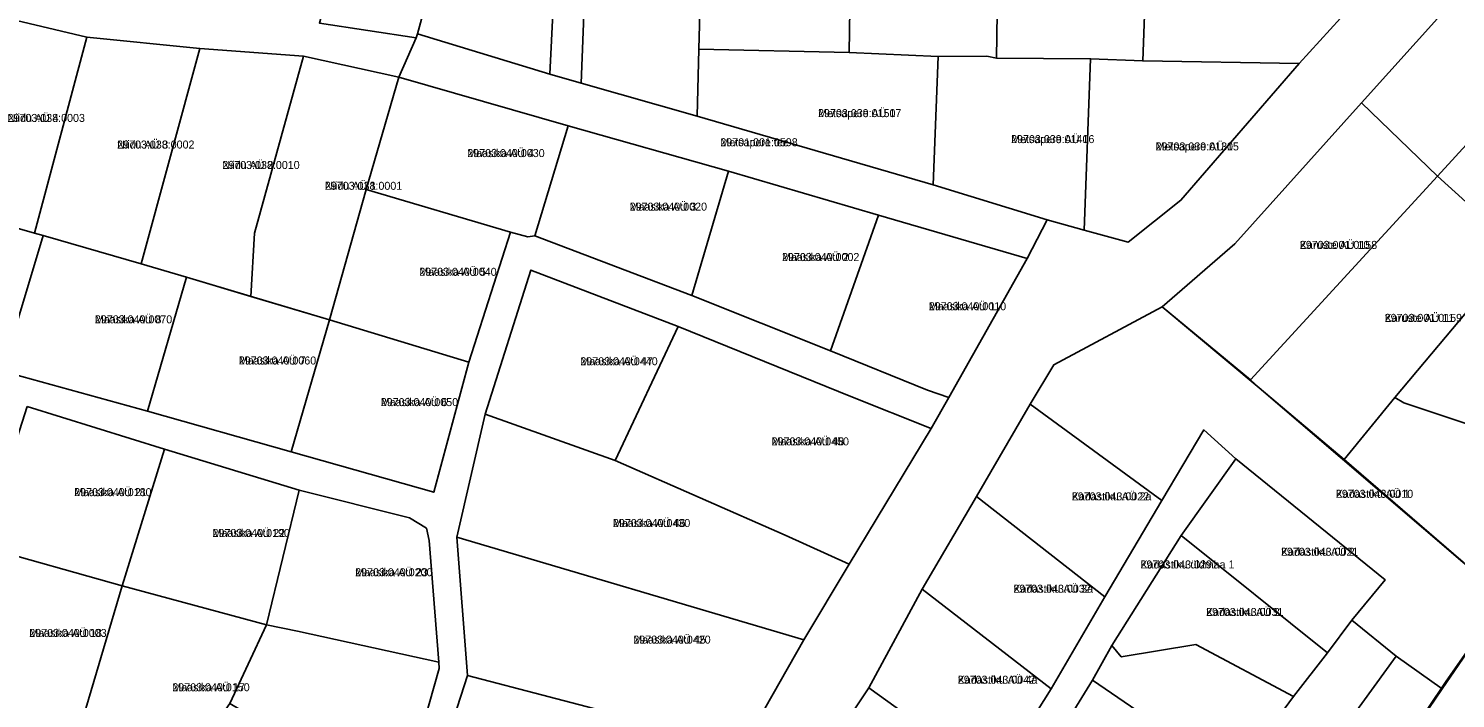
# Model space of a CAD drawing. Extents: x 504287 to 537970, y 6539941 to 6586214.
# Drawn here: x 519484 to 519751.5, y 6560529.1 to 6560654.7 of the extents above; entities that cross this region are included whole.
import ezdxf

# ---------------------------------------------------------------- set-up
doc = ezdxf.new("R2010")
doc.units = 0
for name, color, linetype in [('L_AADRESS', 7, 'Continuous'), ('PIIR', 7, 'Continuous'), ('TUNNUS', 7, 'Continuous')]:
    doc.layers.add(name, color=color, linetype=linetype)

msp = doc.modelspace()

# ---------------------------------------------------------------- linework, layer by layer
at = {"layer": 'PIIR'}
for points in [[(519545.97, 6560683.73), (519553.91, 6560699.22), (519557.93, 6560704.58), (519570.16, 6560715.51), (519573.25, 6560713.46), (519565.9, 6560686.67), (519556.9, 6560653.64), (519556.68, 6560652.92), (519538.51, 6560655.67)], [(519583.75, 6560686.55), (519581.71, 6560646.09), (519556.9, 6560653.64), (519565.9, 6560686.67)], [(519588.8, 6560675), (519593.29, 6560680.01), (519610.46, 6560680.42), (519609.63, 6560650.78), (519609.34, 6560638.23), (519587.61, 6560644.43)], [(519610.46, 6560680.42), (519637.77, 6560679.93), (519638.26, 6560678.69), (519637.86, 6560650.16), (519609.63, 6560650.78)], [(519638.26, 6560678.69), (519665.88, 6560678.74), (519665.47, 6560649.08), (519663.63, 6560649.49), (519654.54, 6560649.41), (519637.86, 6560650.16)], [(519665.88, 6560678.74), (519693.95, 6560677.88), (519692.88, 6560648.58), (519683.09, 6560649), (519665.47, 6560649.08)], [(519693.95, 6560677.88), (519708.11, 6560677.84), (519729.98, 6560656.58), (519722.23, 6560648.11), (519692.88, 6560648.58)], [(519758.97, 6560668.59), (519775.14, 6560656.47), (519748.13, 6560626.98), (519733.89, 6560640.72)], [(519465.19, 6560621.98), (519475.62, 6560657.61), (519494.94, 6560653.06), (519485.11, 6560616.29), (519474.38, 6560619.37)], [(519775.14, 6560656.47), (519790.1, 6560645.25), (519763.37, 6560613.2), (519748.13, 6560626.98)], [(519485.11, 6560616.29), (519494.94, 6560653.06), (519516.09, 6560650.93), (519505.1, 6560610.52), (519486.72, 6560615.84)], [(519556.68, 6560652.92), (519556.9, 6560653.64), (519581.71, 6560646.09), (519587.61, 6560644.43), (519609.34, 6560638.23), (519653.58, 6560625.33), (519674.93, 6560618.79), (519671.23, 6560611.54), (519643.32, 6560619.67), (519615.22, 6560627.91), (519585.19, 6560636.42), (519553.44, 6560645.52)], [(519505.1, 6560610.52), (519516.09, 6560650.93), (519535.54, 6560649.45), (519526.34, 6560616.28), (519525.67, 6560604.45), (519513.58, 6560608.07)], [(519526.34, 6560616.28), (519535.54, 6560649.45), (519553.44, 6560645.52), (519547.32, 6560624.51), (519540.44, 6560600.03), (519525.67, 6560604.45)], [(519609.63, 6560650.78), (519637.86, 6560650.16), (519654.54, 6560649.41), (519653.58, 6560625.33), (519609.34, 6560638.23)], [(519674.93, 6560618.79), (519653.58, 6560625.33), (519654.54, 6560649.41), (519663.63, 6560649.49), (519665.47, 6560649.08), (519683.09, 6560649), (519681.89, 6560616.88)], [(519722.23, 6560648.11), (519700.04, 6560622.46), (519690.16, 6560614.62), (519681.89, 6560616.88), (519683.09, 6560649), (519692.88, 6560648.58)], [(519553.44, 6560645.52), (519585.19, 6560636.42), (519578.93, 6560615.81), (519577.6, 6560615.6), (519574.35, 6560616.46), (519547.32, 6560624.51)], [(519790.1, 6560645.25), (519792.1, 6560643.72), (519790.9, 6560641.63), (519782.76, 6560605.26), (519775.79, 6560574.07), (519768.41, 6560575.6), (519741.84, 6560584.51), (519740.15, 6560585.49), (519763.37, 6560613.2)], [(519733.89, 6560640.72), (519748.13, 6560626.98), (519713.09, 6560588.78), (519696.51, 6560602.52), (519710.13, 6560614.32)], [(519585.19, 6560636.42), (519615.22, 6560627.91), (519608.32, 6560604.61), (519578.93, 6560615.81)], [(519615.22, 6560627.91), (519643.32, 6560619.67), (519634.31, 6560594.22), (519608.32, 6560604.61)], [(519547.32, 6560624.51), (519574.35, 6560616.46), (519566.52, 6560592.11), (519540.44, 6560600.03)], [(519748.13, 6560626.98), (519763.37, 6560613.2), (519740.15, 6560585.49), (519730.65, 6560573.89), (519714.73, 6560587.31), (519713.09, 6560588.78)], [(519459.75, 6560623.53), (519465.19, 6560621.98), (519474.38, 6560619.37), (519485.11, 6560616.29), (519486.72, 6560615.84), (519479.12, 6560590.42), (519451.97, 6560598.83)], [(519634.31, 6560594.22), (519643.32, 6560619.67), (519671.23, 6560611.54), (519656.53, 6560585.5), (519652.5, 6560586.87)], [(519486.72, 6560615.84), (519505.1, 6560610.52), (519513.58, 6560608.07), (519506.3, 6560582.95), (519479.12, 6560590.42)], [(519578.18, 6560609.38), (519605.78, 6560598.8), (519593.95, 6560573.7), (519569.61, 6560582.35)], [(519513.58, 6560608.07), (519540.44, 6560600.03), (519533.25, 6560575.28), (519506.3, 6560582.95)], [(519696.51, 6560602.52), (519714.73, 6560587.31), (519760.67, 6560547.92), (519749.01, 6560530.86), (519740.41, 6560536.98), (519732.08, 6560543.74), (519738.31, 6560551.32), (519710.34, 6560574.02), (519704.32, 6560579.41), (519696.48, 6560566.19), (519671.78, 6560584.27), (519676.22, 6560591.64)], [(519540.44, 6560600.03), (519566.52, 6560592.11), (519559.96, 6560567.73), (519533.25, 6560575.28)], [(519605.78, 6560598.8), (519638.16, 6560585.71), (519653.23, 6560579.69), (519637.86, 6560554.23), (519625.83, 6560559.7), (519593.95, 6560573.7)], [(519671.78, 6560584.27), (519696.48, 6560566.19), (519685.78, 6560548.14), (519661.74, 6560566.94)], [(519740.15, 6560585.49), (519741.84, 6560584.51), (519768.41, 6560575.6), (519775.79, 6560574.07), (519779.93, 6560573.6), (519772.35, 6560544.8), (519760.67, 6560547.92), (519730.65, 6560573.89)], [(519483.75, 6560583.81), (519509.49, 6560575.79), (519501.54, 6560550.19), (519475.31, 6560557.55)], [(519569.61, 6560582.35), (519593.95, 6560573.7), (519625.83, 6560559.7), (519637.86, 6560554.23), (519629.31, 6560540.07), (519564.26, 6560559.32)], [(519509.49, 6560575.79), (519534.7, 6560568.1), (519528.63, 6560542.91), (519501.54, 6560550.19)], [(519710.34, 6560574.02), (519738.31, 6560551.32), (519732.08, 6560543.74), (519727.5, 6560537.65), (519700.08, 6560559.64)], [(519528.63, 6560542.91), (519534.7, 6560568.1), (519555.39, 6560562.91), (519558.59, 6560560.98), (519559.1, 6560558.72), (519560.92, 6560535.88), (519534.41, 6560541.68)], [(519661.74, 6560566.94), (519685.78, 6560548.14), (519675.73, 6560530.86), (519651.54, 6560549.59)], [(519466.73, 6560529.79), (519475.31, 6560557.55), (519501.54, 6560550.19), (519493.26, 6560522.11), (519482.99, 6560526.65)], [(519564.26, 6560559.32), (519629.31, 6560540.07), (519617.6, 6560519.39), (519596.92, 6560525.41), (519566.31, 6560533.39)], [(519700.08, 6560559.64), (519727.5, 6560537.65), (519721.17, 6560529.45), (519702.86, 6560539.2), (519688.86, 6560536.86), (519687.1, 6560538.98)], [(519501.54, 6560550.19), (519528.63, 6560542.91), (519521.74, 6560528.12), (519511.51, 6560513.6), (519509.75, 6560512.35), (519493.26, 6560522.11)], [(519651.54, 6560549.59), (519675.73, 6560530.86), (519665.15, 6560514.09), (519641.52, 6560531.1)], [(519521.74, 6560528.12), (519528.63, 6560542.91), (519534.41, 6560541.68), (519560.92, 6560535.88), (519560.97, 6560534.7), (519557.09, 6560521.02), (519548.79, 6560510.86), (519532.38, 6560521.8)], [(519706.2, 6560516.97), (519709.33, 6560513.37), (519721.17, 6560529.45), (519727.5, 6560537.65), (519732.08, 6560543.74), (519740.41, 6560536.98), (519701.98, 6560484.01), (519687.73, 6560493.58)], [(519687.1, 6560538.98), (519688.86, 6560536.86), (519702.86, 6560539.2), (519721.17, 6560529.45), (519709.33, 6560513.37), (519706.2, 6560516.97), (519683.46, 6560532.48)], [(519740.41, 6560536.98), (519749.01, 6560530.86), (519722.54, 6560491.81), (519721.71, 6560469.51), (519720.49, 6560468.45), (519701.98, 6560484.01)], [(519566.31, 6560533.39), (519596.92, 6560525.41), (519617.6, 6560519.39), (519601.54, 6560491.69), (519560.51, 6560515.59)], [(519683.46, 6560532.48), (519706.2, 6560516.97), (519672.52, 6560507.08), (519669.12, 6560509.28)]]:
    msp.add_lwpolyline(points, close=True, dxfattribs=at)
for points in [[(519588.8, 6560675), (519587.61, 6560644.43), (519581.71, 6560646.09), (519583.75, 6560686.55)], [(519758.97, 6560668.59), (519733.89, 6560640.72), (519710.13, 6560614.32), (519696.51, 6560602.52), (519676.22, 6560591.64), (519671.78, 6560584.27), (519661.74, 6560566.94), (519651.54, 6560549.59), (519641.52, 6560531.1), (519637.54, 6560525.07), (519619.51, 6560495.06), (519601.79, 6560464.9), (519597.62, 6560457.87), (519583.8, 6560445.64), (519571.46, 6560440.43), (519547, 6560424.1), (519538.39, 6560413.48), (519516.93, 6560385.7), (519503.46, 6560367.79), (519487.87, 6560351.07), (519467.89, 6560339.35)], [(519538.51, 6560655.67), (519556.68, 6560652.92), (519553.44, 6560645.52), (519535.54, 6560649.45), (519516.09, 6560650.93), (519494.94, 6560653.06), (519475.62, 6560657.61)], [(519476.35, 6560360.51), (519492.61, 6560372.35), (519498.16, 6560379.12), (519511.54, 6560396.76), (519526.77, 6560415.79), (519537.12, 6560428.03), (519550.29, 6560439.35), (519558.78, 6560445.49), (519583.53, 6560463.78), (519586.02, 6560465.87), (519589.85, 6560471.99), (519601.54, 6560491.69), (519617.6, 6560519.39), (519629.31, 6560540.07), (519637.86, 6560554.23), (519653.23, 6560579.69), (519656.53, 6560585.5), (519671.23, 6560611.54), (519674.93, 6560618.79), (519681.89, 6560616.88), (519690.16, 6560614.62), (519700.04, 6560622.46), (519722.23, 6560648.11), (519729.98, 6560656.58)], [(519479.12, 6560590.42), (519506.3, 6560582.95), (519533.25, 6560575.28), (519559.96, 6560567.73), (519566.52, 6560592.11), (519574.35, 6560616.46), (519577.6, 6560615.6), (519578.93, 6560615.81), (519608.32, 6560604.61), (519634.31, 6560594.22), (519652.5, 6560586.87), (519656.53, 6560585.5), (519653.23, 6560579.69), (519638.16, 6560585.71), (519605.78, 6560598.8), (519578.18, 6560609.38), (519569.61, 6560582.35), (519564.26, 6560559.32), (519566.31, 6560533.39), (519560.51, 6560515.59)], [(519482.99, 6560526.65), (519493.26, 6560522.11), (519509.75, 6560512.35), (519511.51, 6560513.6), (519519.61, 6560505.79), (519530.53, 6560492.35), (519537.53, 6560498.72), (519544.75, 6560505.81), (519548.79, 6560510.86), (519557.09, 6560521.02), (519560.97, 6560534.7), (519560.92, 6560535.88), (519559.1, 6560558.72), (519558.59, 6560560.98), (519555.39, 6560562.91), (519534.7, 6560568.1), (519509.49, 6560575.79), (519483.75, 6560583.81)], [(519637.54, 6560525.07), (519641.52, 6560531.1), (519665.15, 6560514.09), (519675.73, 6560530.86), (519685.78, 6560548.14), (519696.48, 6560566.19), (519704.32, 6560579.41), (519710.34, 6560574.02), (519700.08, 6560559.64), (519687.1, 6560538.98), (519683.46, 6560532.48), (519669.12, 6560509.28)], [(519703.18, 6560322.99), (519713.19, 6560344.19), (519691.96, 6560356.34), (519698.12, 6560365.63), (519712.14, 6560374.97), (519724.32, 6560363.49), (519737.28, 6560371.88), (519762.93, 6560388.21), (519782.49, 6560401.44), (519769.22, 6560411.65), (519785.83, 6560421.92), (519748.28, 6560451.06), (519742.16, 6560456.22), (519722.85, 6560470.8), (519723.75, 6560493.59), (519749.63, 6560532.14), (519760.67, 6560547.92), (519772.35, 6560544.8), (519797.54, 6560537.62), (519829.04, 6560528.69), (519858.47, 6560520.41), (519883.63, 6560513.22), (519926.01, 6560463.67)]]:
    msp.add_lwpolyline(points, dxfattribs=at)

# ---------------------------------------------------------------- texts
at = {"layer": 'L_AADRESS'}
for s, p in [('Niidu AÜ 4', (519480.06, 6560637.15)), ('Metsapere AÜ 17', (519632.01, 6560638.05)), ('Niidu AÜ 3', (519500.6, 6560632.16)), ('Metsapere tee', (519613.69, 6560632.59)), ('Metsapere AÜ 16', (519668.2, 6560633.18)), ('Metsapere AÜ 15', (519695.29, 6560631.81)), ('Niidu AÜ 2', (519520.32, 6560628.33)), ('Maasika AÜ 4', (519566.25, 6560630.56)), ('Niidu AÜ 1', (519539.55, 6560624.43)), ('Maasika AÜ 3', (519596.69, 6560620.52)), ('Karuste AÜ 10', (519722.32, 6560613.35)), ('Maasika AÜ 2', (519625.25, 6560611.07)), ('Maasika AÜ 5', (519557.25, 6560608.31)), ('Maasika AÜ 1', (519652.77, 6560601.85)), ('Maasika AÜ 8', (519496.43, 6560599.4)), ('Karuste AÜ 11', (519738.23, 6560599.67)), ('Maasika AÜ 7', (519523.42, 6560591.68)), ('Maasika AÜ 47', (519587.44, 6560591.54)), ('Maasika AÜ 6', (519550.03, 6560583.88)), ('Maasika AÜ 48', (519623.3, 6560576.52)), ('Maasika AÜ 21', (519492.55, 6560567)), ('Kadastiku AÜ 1', (519729.08, 6560566.69)), ('Kadastiku AÜ 2a', (519679.57, 6560566.21)), ('Maasika AÜ 46', (519593.55, 6560561.21)), ('Maasika AÜ 22', (519518.49, 6560559.35)), ('Kadastiku AÜ 2', (519718.79, 6560555.83)), ('Kadastiku üldmaa 1', (519692.45, 6560553.45)), ('Maasika AÜ 23', (519545.23, 6560551.99)), ('Kadastiku AÜ 3a', (519668.62, 6560548.9)), ('Kadastiku AÜ 3', (519704.75, 6560544.54)), ('Maasika AÜ 18', (519484.13, 6560540.61)), ('Maasika AÜ 45', (519597.37, 6560539.36)), ('Kadastiku AÜ 4a', (519658.19, 6560531.84)), ('Maasika AÜ 17', (519510.95, 6560530.43))]:
    msp.add_text(s, height=1.5, dxfattribs=at).set_placement(p)
at = {"layer": 'TUNNUS'}
for s, p in [('29703:038:0003', (519480.06, 6560637.15)), ('29703:039:0150', (519632.01, 6560638.05)), ('29703:038:0002', (519500.6, 6560632.16)), ('29701:001:0598', (519613.69, 6560632.59)), ('29703:039:0140', (519668.2, 6560633.18)), ('29703:039:0130', (519695.29, 6560631.81)), ('29703:038:0010', (519520.32, 6560628.33)), ('29703:040:0030', (519566.25, 6560630.56)), ('29703:038:0001', (519539.55, 6560624.43)), ('29703:040:0020', (519596.69, 6560620.52)), ('29703:001:0158', (519722.32, 6560613.35)), ('29703:040:0002', (519625.25, 6560611.07)), ('29703:040:0040', (519557.25, 6560608.31)), ('29703:040:0010', (519652.77, 6560601.85)), ('29703:040:0070', (519496.43, 6560599.4)), ('29703:001:0159', (519738.23, 6560599.67)), ('29703:040:0060', (519523.42, 6560591.68)), ('29703:040:0440', (519587.44, 6560591.54)), ('29703:040:0050', (519550.03, 6560583.88)), ('29703:040:0450', (519623.3, 6560576.52)), ('29703:040:0180', (519492.55, 6560567)), ('29703:043:0010', (519729.08, 6560566.69)), ('29703:043:0022', (519679.57, 6560566.21)), ('29703:040:0190', (519518.49, 6560559.35)), ('29703:040:0430', (519593.55, 6560561.21)), ('29703:043:0291', (519692.45, 6560553.45)), ('29703:043:0021', (519718.79, 6560555.83)), ('29703:040:0200', (519545.23, 6560551.99)), ('29703:043:0032', (519668.62, 6560548.9)), ('29703:043:0031', (519704.75, 6560544.54)), ('29703:040:0003', (519484.13, 6560540.61)), ('29703:040:0420', (519597.37, 6560539.36)), ('29703:040:0150', (519510.95, 6560530.43)), ('29703:043:0042', (519658.19, 6560531.84))]:
    msp.add_text(s, height=1.5, dxfattribs=at).set_placement(p)

doc.saveas('drawing.dxf')
